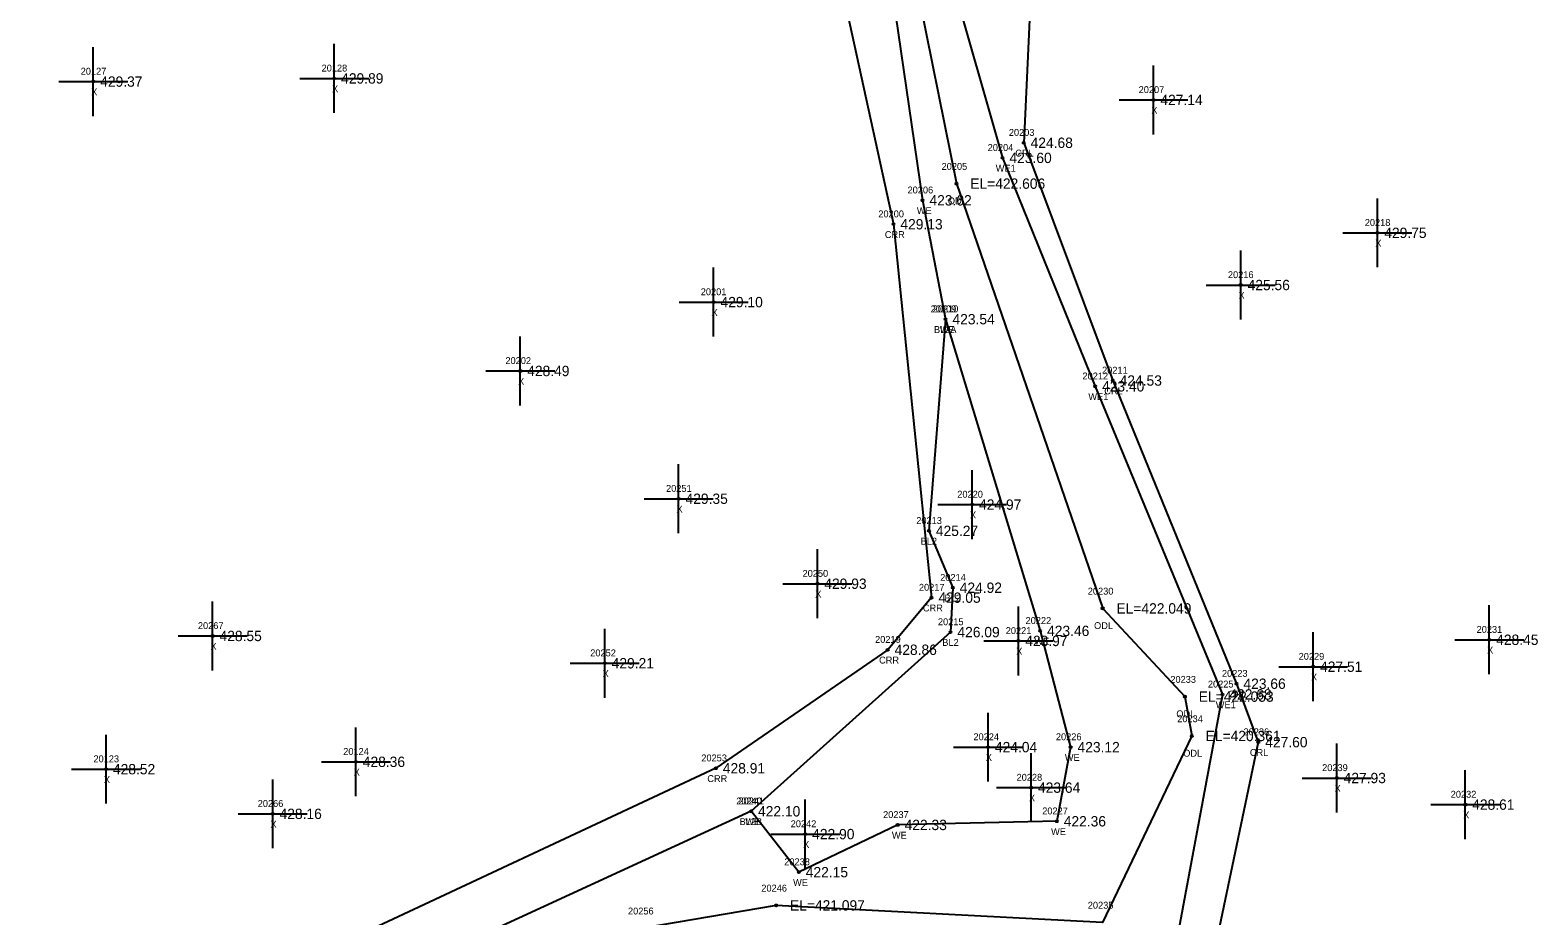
# Model space of a CAD drawing. Extents: x 1858461 to 1858936, y 1147060 to 1148183.
# Drawn here: x 1858716.7 to 1858935.5, y 1147747.9 to 1147876.4 of the extents above; entities that cross this region are included whole.
import ezdxf

# ---------------------------------------------------------------- set-up
doc = ezdxf.new("R2010")
doc.units = 0
for name, color, linetype in [('RD_DTM_BkLn1', 7, 'Continuous'), ('RD_DTM_BkLn_txCode', 7, 'Continuous'), ('RD_EX_H2O', 7, 'Continuous'), ('RD_EX_H2O_txCode', 7, 'Continuous'), ('RD_EX_Misc', 7, 'Continuous'), ('RD_EX_Misc_txCode', 7, 'Continuous'), ('RD_EX_TX_H2O_ELEV', 7, 'Continuous'), ('RD_EX_TX_Misc_ELEV', 7, 'Continuous'), ('RD_SMD_Locator', 7, 'Continuous')]:
    doc.layers.add(name, color=color, linetype=linetype)

msp = doc.modelspace()

# ---------------------------------------------------------------- linework, layer by layer
at = {"layer": 'RD_DTM_BkLn1'}
msp.add_lwpolyline([(1858849.56, 1147834.44), (1858847.15, 1147803.73), (1858850.61, 1147795.48), (1858850.28, 1147789.04), (1858821.34, 1147763.04)], dxfattribs=at)
at = {"layer": 'RD_EX_H2O'}
for points in [[(1858883.69, 1148147.48), (1858852.78, 1148112.64), (1858836.04, 1148037.73), (1858833.26, 1147975.2), (1858828.33, 1147910.84), (1858842, 1147848.22), (1858847.52, 1147794.04), (1858841.16, 1147786.48), (1858816.23, 1147769.28), (1858759.58, 1147742.8), (1858751.47, 1147732.35), (1858731.2, 1147689.66), (1858724.77, 1147677.64), (1858718.76, 1147662.14), (1858713.87, 1147646.5), (1858696.23, 1147629.99), (1858681.73, 1147631.9), (1858663.61, 1147613.98)], [(1858909.91, 1148115.72), (1858902.77, 1148116.75), (1858903.07, 1148125.04), (1858896.61, 1148132.76), (1858873.78, 1148129.33), (1858855.27, 1148111.83), (1858840.09, 1148036.93), (1858846.14, 1147982.36), (1858846.9, 1147967.54), (1858840.1, 1147928.32), (1858835.96, 1147922.3), (1858846.22, 1147851.69), (1858849.56, 1147834.44), (1858863.29, 1147789.22), (1858867.71, 1147772.35), (1858865.71, 1147761.59), (1858842.61, 1147761.06), (1858828.27, 1147754.21), (1858821.34, 1147763.04), (1858764.94, 1147737.1), (1858734.3, 1147688.97), (1858719.03, 1147640.86), (1858697.04, 1147613.49)], [(1858867.04, 1148108.26), (1858855.22, 1148032.48), (1858854.94, 1147976.71), (1858844.75, 1147924.02), (1858838.88, 1147914.94), (1858851.14, 1147854.11), (1858872.36, 1147792.48), (1858884.3, 1147779.68), (1858885.3, 1147773.97), (1858872.32, 1147746.91), (1858824.97, 1147749.39), (1858805.62, 1147746.07), (1858768.36, 1147727.81), (1858744.99, 1147687.5), (1858739.82, 1147673.18), (1858724.58, 1147638.24), (1858698.73, 1147607.87)], [(1858878.92, 1148104.66), (1858861.55, 1148027.41), (1858861.16, 1147976.95), (1858850.44, 1147924.2), (1858843.19, 1147917.77), (1858850.23, 1147884.47), (1858857.83, 1147857.85), (1858871.27, 1147824.7), (1858889.75, 1147780), (1858881.97, 1147738.22), (1858867.37, 1147736.75), (1858826.32, 1147742.88), (1858795.91, 1147734.53), (1858775.64, 1147718.51), (1858753.77, 1147690.47), (1858731.96, 1147634.67), (1858700.72, 1147599.99)], [(1858879.83, 1148102.54), (1858871.42, 1148034.27), (1858866.93, 1147971.73), (1858863.21, 1147909.44), (1858860.9, 1147860.04), (1858873.82, 1147825.54), (1858891.79, 1147781.55), (1858894.95, 1147773.07), (1858887.01, 1147735.25), (1858825.08, 1147733.03), (1858791.14, 1147702.41), (1858765.02, 1147654.77), (1858740.99, 1147628.76), (1858706.35, 1147596.83), (1858671.87, 1147580.02), (1858637.61, 1147560.56), (1858613.46, 1147539.88), (1858609.2, 1147499), (1858608.26, 1147474.71), (1858583.43, 1147442.99), (1858542.68, 1147417.32), (1858497.34, 1147430.55)]]:
    msp.add_lwpolyline(points, dxfattribs=at)
at = {"layer": 'RD_EX_Misc'}
for p, q in [((1858725.87, 1147863.92), (1858725.87, 1147873.92)), ((1858760.84, 1147864.38), (1858760.84, 1147874.38)), ((1858755.84, 1147869.38), (1858765.84, 1147869.38)), ((1858879.73, 1147861.25), (1858879.73, 1147871.25)), ((1858720.87, 1147868.92), (1858730.87, 1147868.92)), ((1858874.73, 1147866.25), (1858884.73, 1147866.25)), ((1858912.23, 1147841.97), (1858912.23, 1147851.97)), ((1858907.23, 1147846.97), (1858917.23, 1147846.97)), ((1858892.39, 1147834.4), (1858892.39, 1147844.4)), ((1858815.9, 1147831.92), (1858815.9, 1147841.92)), ((1858887.39, 1147839.4), (1858897.39, 1147839.4)), ((1858810.9, 1147836.92), (1858820.9, 1147836.92)), ((1858787.84, 1147821.93), (1858787.84, 1147831.93)), ((1858782.84, 1147826.93), (1858792.84, 1147826.93)), ((1858810.82, 1147803.39), (1858810.82, 1147813.39)), ((1858853.42, 1147802.54), (1858853.42, 1147812.54)), ((1858805.82, 1147808.39), (1858815.82, 1147808.39)), ((1858848.42, 1147807.54), (1858858.42, 1147807.54)), ((1858830.96, 1147791.06), (1858830.96, 1147801.06)), ((1858825.96, 1147796.06), (1858835.96, 1147796.06)), ((1858743.19, 1147783.48), (1858743.19, 1147793.48)), ((1858860.12, 1147782.76), (1858860.12, 1147792.76)), ((1858928.47, 1147782.93), (1858928.47, 1147792.93)), ((1858738.19, 1147788.48), (1858748.19, 1147788.48)), ((1858800.1, 1147779.52), (1858800.1, 1147789.52)), ((1858902.91, 1147779.02), (1858902.91, 1147789.02)), ((1858855.12, 1147787.76), (1858865.12, 1147787.76)), ((1858923.47, 1147787.93), (1858933.47, 1147787.93)), ((1858795.1, 1147784.52), (1858805.1, 1147784.52)), ((1858897.91, 1147784.02), (1858907.91, 1147784.02)), ((1858855.72, 1147767.35), (1858855.72, 1147777.35)), ((1858727.72, 1147764.15), (1858727.72, 1147774.15)), ((1858763.98, 1147765.22), (1858763.98, 1147775.22)), ((1858850.72, 1147772.35), (1858860.72, 1147772.35)), ((1858861.97, 1147761.47), (1858861.97, 1147771.47)), ((1858906.33, 1147762.87), (1858906.33, 1147772.87)), ((1858722.72, 1147769.15), (1858732.72, 1147769.15)), ((1858758.98, 1147770.22), (1858768.98, 1147770.22)), ((1858924.99, 1147759.01), (1858924.99, 1147769.01)), ((1858751.9, 1147757.67), (1858751.9, 1147767.67)), ((1858901.33, 1147767.87), (1858911.33, 1147767.87)), ((1858829.2, 1147754.73), (1858829.2, 1147764.73)), ((1858856.97, 1147766.47), (1858866.97, 1147766.47)), ((1858746.9, 1147762.67), (1858756.9, 1147762.67)), ((1858919.99, 1147764.01), (1858929.99, 1147764.01)), ((1858824.2, 1147759.73), (1858834.2, 1147759.73))]:
    msp.add_line(p, q, dxfattribs=at)
at = {"layer": 'RD_SMD_Locator'}
for centre in [(1858760.84, 1147869.38), (1858725.87, 1147868.92), (1858879.73, 1147866.25), (1858860.9, 1147860.04), (1858857.83, 1147857.85), (1858851.14, 1147854.11), (1858846.22, 1147851.69), (1858842, 1147848.22), (1858912.23, 1147846.97), (1858892.39, 1147839.4), (1858815.9, 1147836.92), (1858849.56, 1147834.44), (1858849.56, 1147834.44), (1858787.84, 1147826.93), (1858873.82, 1147825.54), (1858871.27, 1147824.7), (1858810.82, 1147808.39), (1858853.42, 1147807.54), (1858847.15, 1147803.73), (1858830.96, 1147796.06), (1858850.61, 1147795.48), (1858847.52, 1147794.04), (1858872.36, 1147792.48), (1858743.19, 1147788.48), (1858850.28, 1147789.04), (1858863.29, 1147789.22), (1858841.16, 1147786.48), (1858860.12, 1147787.76), (1858928.47, 1147787.93), (1858800.1, 1147784.52), (1858902.91, 1147784.02), (1858884.3, 1147779.68), (1858889.75, 1147780), (1858891.79, 1147781.55), (1858885.3, 1147773.97), (1858894.95, 1147773.07), (1858855.72, 1147772.35), (1858867.71, 1147772.35), (1858727.72, 1147769.15), (1858763.98, 1147770.22), (1858816.23, 1147769.28), (1858861.97, 1147766.47), (1858906.33, 1147767.87), (1858751.9, 1147762.67), (1858821.34, 1147763.04), (1858821.34, 1147763.04), (1858924.99, 1147764.01), (1858842.61, 1147761.06), (1858865.71, 1147761.59), (1858829.2, 1147759.73), (1858828.27, 1147754.21), (1858824.97, 1147749.39)]:
    msp.add_circle(centre, 0.15, dxfattribs=at)

# ---------------------------------------------------------------- texts
at = {"layer": 'RD_DTM_BkLn_txCode'}
for s, p in [('20210', (1858847.69, 1147835.44)), ('BL2A', (1858847.87, 1147832.44)), ('20213', (1858845.31, 1147804.73)), ('BL2', (1858845.94, 1147801.73)), ('20214', (1858848.78, 1147796.48)), ('BL2', (1858849.41, 1147793.48)), ('20215', (1858848.45, 1147790.04)), ('BL2', (1858849.08, 1147787.04)), ('20241', (1858819.5, 1147764.04)), ('BL2B', (1858819.66, 1147761.04))]:
    msp.add_text(s, height=1, dxfattribs=at).set_placement(p)
at = {"layer": 'RD_EX_H2O_txCode'}
for s, p in [('20203', (1858858.74, 1147861.04)), ('20204', (1858855.67, 1147858.85)), ('CRL', (1858859.67, 1147858.04)), ('20205', (1858848.98, 1147856.11)), ('WE1', (1858856.84, 1147855.85)), ('20206', (1858844.04, 1147852.69)), ('ODL', (1858849.89, 1147851.11)), ('20200', (1858839.8, 1147849.22)), ('WE', (1858845.39, 1147849.69)), ('CRR', (1858840.74, 1147846.22)), ('20209', (1858847.4, 1147835.44)), ('WE', (1858848.72, 1147832.44)), ('20212', (1858869.43, 1147825.7)), ('20211', (1858872.27, 1147826.54)), ('WE1', (1858870.28, 1147822.7)), ('CRL', (1858872.59, 1147823.54)), ('20217', (1858845.69, 1147795.04)), ('20230', (1858870.2, 1147794.48)), ('CRR', (1858846.27, 1147792.04)), ('20222', (1858861.17, 1147790.22)), ('20219', (1858839.33, 1147787.48)), ('ODL', (1858871.11, 1147789.48)), ('WE', (1858862.45, 1147787.22)), ('CRR', (1858839.91, 1147784.48)), ('20233', (1858882.18, 1147781.68)), ('20225', (1858887.63, 1147781)), ('20223', (1858889.67, 1147782.55)), ('CRL', (1858890.56, 1147779.55)), ('ODL', (1858883.05, 1147776.68)), ('WE1', (1858888.77, 1147778)), ('20234', (1858883.18, 1147775.97)), ('20226', (1858865.57, 1147773.35)), ('20236', (1858892.8, 1147774.07)), ('20253', (1858814.11, 1147770.28)), ('WE', (1858866.87, 1147770.35)), ('ODL', (1858884.05, 1147770.97)), ('CRL', (1858893.72, 1147771.07)), ('CRR', (1858814.98, 1147767.28)), ('20240', (1858819.18, 1147764.04)), ('20237', (1858840.49, 1147762.06)), ('20227', (1858863.59, 1147762.59)), ('WE', (1858820.5, 1147761.04)), ('WE', (1858841.77, 1147759.06)), ('WE', (1858864.87, 1147759.59)), ('20238', (1858826.15, 1147755.21)), ('20246', (1858822.82, 1147751.39)), ('WE', (1858827.43, 1147752.21)), ('20256', (1858803.47, 1147748.07)), ('20235', (1858870.2, 1147748.91))]:
    msp.add_text(s, height=1, dxfattribs=at).set_placement(p)
at = {"layer": 'RD_EX_Misc_txCode'}
for s, p in [('20127', (1858724.04, 1147869.92)), ('20128', (1858759, 1147870.38)), ('X', (1858725.56, 1147866.92)), ('X', (1858760.52, 1147867.38)), ('20207', (1858877.58, 1147867.25)), ('X', (1858879.42, 1147864.25)), ('20218', (1858910.4, 1147847.97)), ('X', (1858911.92, 1147844.97)), ('20216', (1858890.54, 1147840.4)), ('20201', (1858814.03, 1147837.92)), ('X', (1858892.08, 1147837.4)), ('X', (1858815.59, 1147834.92)), ('20202', (1858785.68, 1147827.93)), ('X', (1858787.52, 1147824.93)), ('20251', (1858808.99, 1147809.39)), ('20220', (1858851.26, 1147808.54)), ('X', (1858810.51, 1147806.39)), ('X', (1858853.1, 1147805.54)), ('20250', (1858828.8, 1147797.06)), ('X', (1858830.65, 1147794.06)), ('20267', (1858741.05, 1147789.48)), ('20221', (1858858.29, 1147788.76)), ('20231', (1858926.63, 1147788.93)), ('X', (1858742.87, 1147786.48)), ('20252', (1858797.99, 1147785.52)), ('X', (1858859.81, 1147785.76)), ('X', (1858928.15, 1147785.93)), ('20229', (1858900.8, 1147785.02)), ('X', (1858799.79, 1147782.52)), ('X', (1858902.6, 1147782.02)), ('20224', (1858853.6, 1147773.35)), ('20123', (1858725.89, 1147770.15)), ('20124', (1858762.14, 1147771.22)), ('X', (1858855.4, 1147770.35)), ('X', (1858763.66, 1147768.22)), ('20239', (1858904.21, 1147768.87)), ('X', (1858727.41, 1147767.15)), ('20228', (1858859.86, 1147767.47)), ('X', (1858906.02, 1147765.87)), ('20266', (1858749.73, 1147763.67)), ('X', (1858861.66, 1147764.47)), ('20232', (1858922.87, 1147765.01)), ('X', (1858924.68, 1147762.01)), ('X', (1858751.58, 1147760.67)), ('20242', (1858827.08, 1147760.73)), ('X', (1858828.89, 1147757.73))]:
    msp.add_text(s, height=1, dxfattribs=at).set_placement(p)
at = {"layer": 'RD_EX_TX_H2O_ELEV'}
for s, p in [('424.68', (1858861.9, 1147859.29)), ('423.60', (1858858.83, 1147857.1)), ('EL=422.606', (1858853.14, 1147853.36)), ('423.62', (1858847.22, 1147850.94)), ('429.13', (1858843, 1147847.47)), ('423.54', (1858850.56, 1147833.69)), ('424.53', (1858874.82, 1147824.79)), ('423.40', (1858872.27, 1147823.95)), ('429.05', (1858848.52, 1147793.29)), ('EL=422.049', (1858874.36, 1147791.73)), ('423.46', (1858864.29, 1147788.47)), ('428.86', (1858842.16, 1147785.73)), ('423.66', (1858892.79, 1147780.8)), ('EL=422.053', (1858886.3, 1147778.93)), ('422.68', (1858890.75, 1147779.25)), ('423.12', (1858868.71, 1147771.6)), ('EL=420.361', (1858887.3, 1147773.22)), ('427.60', (1858895.95, 1147772.32)), ('428.91', (1858817.23, 1147768.53)), ('422.10', (1858822.34, 1147762.29)), ('422.36', (1858866.71, 1147760.84)), ('422.33', (1858843.61, 1147760.31)), ('422.15', (1858829.27, 1147753.46)), ('EL=421.097', (1858826.97, 1147748.64))]:
    msp.add_text(s, height=1.5, dxfattribs=at).set_placement(p)
at = {"layer": 'RD_EX_TX_Misc_ELEV'}
for s, p in [('429.37', (1858726.87, 1147868.17)), ('429.89', (1858761.84, 1147868.63)), ('427.14', (1858880.73, 1147865.5)), ('429.75', (1858913.23, 1147846.22)), ('425.56', (1858893.39, 1147838.65)), ('429.10', (1858816.9, 1147836.17)), ('423.54', (1858850.56, 1147833.69)), ('428.49', (1858788.84, 1147826.18)), ('429.35', (1858811.82, 1147807.64)), ('424.97', (1858854.42, 1147806.79)), ('425.27', (1858848.15, 1147802.98)), ('429.93', (1858831.96, 1147795.31)), ('424.92', (1858851.61, 1147794.73)), ('428.55', (1858744.19, 1147787.73)), ('426.09', (1858851.28, 1147788.29)), ('423.97', (1858861.12, 1147787.01)), ('428.45', (1858929.47, 1147787.18)), ('429.21', (1858801.1, 1147783.77)), ('427.51', (1858903.91, 1147783.27)), ('424.04', (1858856.72, 1147771.6)), ('428.36', (1858764.98, 1147769.47)), ('428.52', (1858728.72, 1147768.4)), ('423.64', (1858862.97, 1147765.72)), ('427.93', (1858907.33, 1147767.12)), ('428.61', (1858925.99, 1147763.26)), ('428.16', (1858752.9, 1147761.92)), ('422.10', (1858822.34, 1147762.29)), ('422.90', (1858830.2, 1147758.98))]:
    msp.add_text(s, height=1.5, dxfattribs=at).set_placement(p)

doc.saveas('drawing.dxf')
